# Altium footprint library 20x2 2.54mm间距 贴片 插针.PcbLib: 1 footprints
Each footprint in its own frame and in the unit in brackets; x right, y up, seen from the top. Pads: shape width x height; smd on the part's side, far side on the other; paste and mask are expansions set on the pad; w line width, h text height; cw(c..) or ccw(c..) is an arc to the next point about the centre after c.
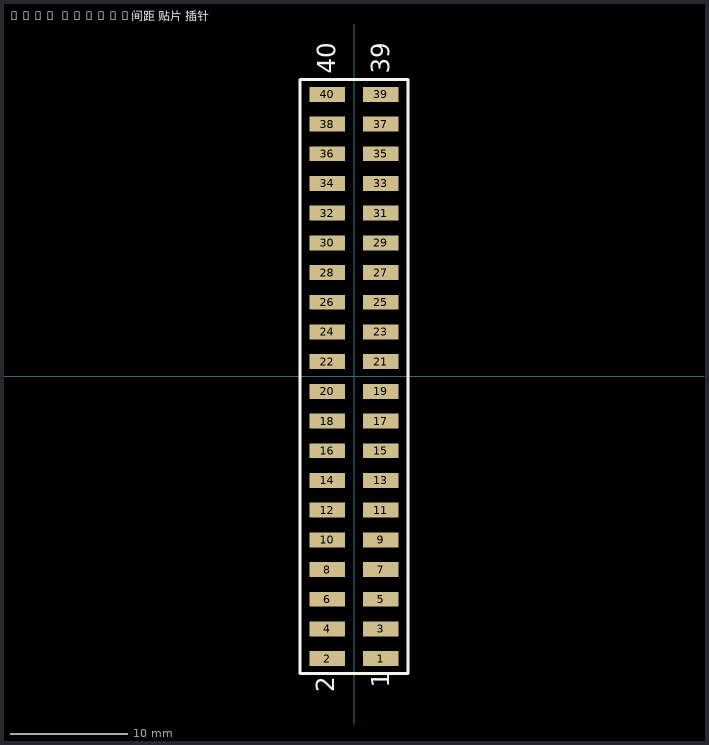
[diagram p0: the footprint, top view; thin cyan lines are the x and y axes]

## 20x2 2.54mm间距 贴片 插针 [mm] "20x2 2.54mm间距 贴片 插针"
pads (40):
  rect 3.05x1.27 smd: 1(2.3,-24.13) 2(-2.3,-24.13) 3(2.3,-21.59) 4(-2.3,-21.59) 5(2.3,-19.05) 6(-2.3,-19.05) 7(2.3,-16.51) 8(-2.3,-16.51) 9(2.3,-13.97) 10(-2.3,-13.97) 11(2.3,-11.43) 12(-2.3,-11.43) 13(2.3,-8.89) 14(-2.3,-8.89) 15(2.3,-6.35) 16(-2.3,-6.35) 17(2.3,-3.81) 18(-2.3,-3.81) 19(2.3,-1.27) 20(-2.3,-1.27) 21(2.3,1.27) 22(-2.3,1.27) 23(2.3,3.81) 24(-2.3,3.81) 25(2.3,6.35) 26(-2.3,6.35) 27(2.3,8.89) 28(-2.3,8.89) 29(2.3,11.43) 30(-2.3,11.43) 31(2.3,13.97) 32(-2.3,13.97) 33(2.3,16.51) 34(-2.3,16.51) 35(2.3,19.05) 36(-2.3,19.05) 37(2.3,21.59) 38(-2.3,21.59) 39(2.3,24.13) 40(-2.3,24.13)
Top Overlay:
  lines w0.254: -4.6,-25.4 4.6,-25.4 4.6,25.4 -4.6,25.4 -4.6,-25.4
  text "40" at -1.6,25.9 h1.52
  text "39" at 3,25.9 h1.52
  text "2" at -1.7,-27 h1.52
  text "1" at 3,-26.6 h1.52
